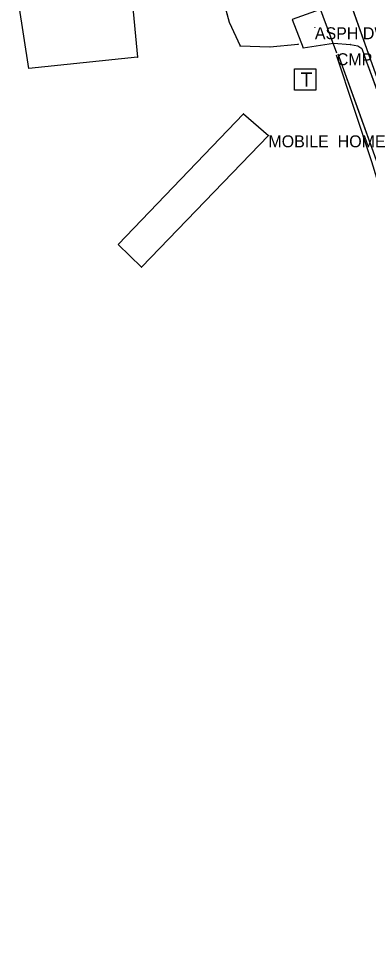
# Model space of a CAD drawing. Extents: x 1050807 to 1053552, y 395828 to 398415.
# Drawn here: x 1052487.3 to 1052633.5, y 395848.9 to 396242.6 of the extents above; entities that cross this region are included whole.
import ezdxf

# ---------------------------------------------------------------- set-up
doc = ezdxf.new("R2010")
doc.units = 0
for name, color, linetype in [('S_BUILDING', 7, 'Continuous'), ('S_BUILDING_ANNOT', 7, 'Continuous'), ('S_DITCHLINE', 7, 'Continuous'), ('S_DRIVEWAY', 7, 'Continuous'), ('S_EDGE_PAVEMENT', 7, 'Continuous'), ('S_MSC_PT_SYM', 7, 'Continuous'), ('S_RDW_PT_SYM', 7, 'Continuous'), ('S_SHOULDER', 7, 'Continuous'), ('S_SIDE_DRAIN', 7, 'Continuous'), ('S_SIDE_DRAIN_ANNOT', 7, 'Continuous'), ('S_STR_PT_SYM', 7, 'Continuous'), ('S_SURVEY_TEXT_ANNOT', 7, 'Continuous'), ('S_TELEPHONE_UTILITIES', 7, 'Continuous')]:
    doc.layers.add(name, color=color, linetype=linetype)

msp = doc.modelspace()

# ---------------------------------------------------------------- linework, layer by layer
at = {"layer": 'S_BUILDING'}
for p, q in [((1052533.83, 396259.23), (1052536.9, 396226.54)), ((1052491.51, 396221.91), (1052487.31, 396248.91)), ((1052536.9, 396226.54), (1052491.51, 396221.91)), ((1052528.92, 396148.24), (1052581.25, 396202.87)), ((1052581.25, 396202.87), (1052591.72, 396193.88)), ((1052591.72, 396193.88), (1052538.7, 396138.79)), ((1052538.7, 396138.79), (1052528.92, 396148.24))]:
    msp.add_line(p, q, dxfattribs=at)
at = {"layer": 'S_DITCHLINE'}
for p, q in [((1052620.07, 396227.58), (1052634.89, 396182.92)), ((1052620.81, 396227.93), (1052636.76, 396183.53))]:
    msp.add_line(p, q, dxfattribs=at)
for points in [[(1052620.07, 396227.58), (1052627.48, 396205.25), (1052634.89, 396182.92), (1052642.05, 396159.3), (1052649.2, 396135.67), (1052656.36, 396112.05), (1052663.51, 396088.42), (1052668.48, 396075.25), (1052673.44, 396062.07), (1052678.41, 396048.9), (1052683.38, 396035.72), (1052688.34, 396022.55), (1052693.31, 396009.37), (1052698.27, 395996.19), (1052703.24, 395983.02), (1052710.64, 395963.11), (1052718.05, 395943.2), (1052725.45, 395923.3), (1052732.85, 395903.39), (1052737.44, 395889.76), (1052742.03, 395876.12), (1052746.61, 395862.49), (1052751.2, 395848.85)], [(1052620.81, 396227.93), (1052628.79, 396205.73), (1052636.76, 396183.53), (1052644, 396159.99), (1052651.24, 396136.44), (1052658.48, 396112.9), (1052665.73, 396089.35), (1052670.69, 396076.19), (1052675.66, 396063.03), (1052680.63, 396049.86), (1052685.59, 396036.7), (1052690.56, 396023.54), (1052695.53, 396010.38), (1052700.49, 395997.21), (1052705.46, 395984.05), (1052713.07, 395964.14), (1052720.69, 395944.23), (1052728.3, 395924.32), (1052735.92, 395904.41), (1052740.3, 395890.61), (1052744.69, 395876.8), (1052749.07, 395863), (1052753.46, 395849.2)]]:
    msp.add_lwpolyline(points, dxfattribs=at)
at = {"layer": 'S_DRIVEWAY'}
for p, q in [((1052572.02, 396253.63), (1052575.27, 396241.22)), ((1052613.38, 396246.47), (1052601.72, 396242.34)), ((1052575.27, 396241.22), (1052579.85, 396231.29)), ((1052601.72, 396242.34), (1052606.28, 396230.47)), ((1052579.85, 396231.29), (1052592.36, 396230.88)), ((1052592.36, 396230.88), (1052604.22, 396232.06)), ((1052606.28, 396230.47), (1052618.94, 396232.39)), ((1052618.94, 396232.39), (1052626, 396231.88)), ((1052626, 396231.88), (1052629.12, 396231.28))]:
    msp.add_line(p, q, dxfattribs=at)
for points in [[(1052582.95, 396285.88), (1052574.93, 396278.66), (1052570.6, 396269.39), (1052572.02, 396253.63), (1052575.27, 396241.22), (1052579.85, 396231.29), (1052592.36, 396230.88), (1052604.22, 396232.06)], [(1052621.14, 396254.58), (1052618.12, 396249.9), (1052613.38, 396246.47), (1052601.72, 396242.34), (1052606.28, 396230.47), (1052618.94, 396232.39), (1052626, 396231.88), (1052629.12, 396231.28)]]:
    msp.add_lwpolyline(points, dxfattribs=at)
at = {"layer": 'S_EDGE_PAVEMENT'}
msp.add_line((1052623.98, 396255.21), (1052634.42, 396225.5), dxfattribs=at)
msp.add_lwpolyline([(1052623.98, 396255.21), (1052629.2, 396240.35), (1052634.42, 396225.5), (1052641.29, 396206.33), (1052648.17, 396187.15), (1052655.4, 396166.58), (1052662.63, 396146), (1052669.81, 396125.89), (1052676.99, 396105.79), (1052684.26, 396085.26), (1052691.54, 396064.73), (1052698.54, 396044.92), (1052705.54, 396025.11), (1052713.26, 396003.75), (1052720.98, 395982.38), (1052728.49, 395960.93), (1052736.01, 395939.48), (1052742.94, 395919.92), (1052749.87, 395900.35), (1052754.46, 395887.56), (1052759.05, 395874.76), (1052766.38, 395854.19)], dxfattribs=at)
at = {"layer": 'S_MSC_PT_SYM'}
msp.add_lwpolyline([(1052611.16, 396239.08), (1052611.16, 396239.13), (1052611.16, 396239.08), (1052611.11, 396239.08), (1052611.16, 396239.08), (1052611.16, 396239.03), (1052611.16, 396239.08), (1052611.21, 396239.08)], dxfattribs=at)
at = {"layer": 'S_RDW_PT_SYM'}
for points in [[(1052575.27, 396241.22), (1052575.27, 396241.27), (1052575.27, 396241.22), (1052575.22, 396241.22), (1052575.27, 396241.22), (1052575.27, 396241.17), (1052575.27, 396241.22), (1052575.32, 396241.22)], [(1052601.72, 396242.34), (1052601.72, 396242.39), (1052601.72, 396242.34), (1052601.67, 396242.34), (1052601.72, 396242.34), (1052601.72, 396242.29), (1052601.72, 396242.34), (1052601.77, 396242.34)], [(1052579.85, 396231.29), (1052579.85, 396231.34), (1052579.85, 396231.29), (1052579.8, 396231.29), (1052579.85, 396231.29), (1052579.85, 396231.24), (1052579.85, 396231.29), (1052579.9, 396231.29)], [(1052604.22, 396232.06), (1052604.22, 396232.11), (1052604.22, 396232.06), (1052604.17, 396232.06), (1052604.22, 396232.06), (1052604.22, 396232.01), (1052604.22, 396232.06), (1052604.27, 396232.06)], [(1052618.94, 396232.39), (1052618.94, 396232.44), (1052618.94, 396232.39), (1052618.89, 396232.39), (1052618.94, 396232.39), (1052618.94, 396232.34), (1052618.94, 396232.39), (1052618.99, 396232.39)], [(1052626, 396231.88), (1052626, 396231.93), (1052626, 396231.88), (1052625.95, 396231.88), (1052626, 396231.88), (1052626, 396231.83), (1052626, 396231.88), (1052626.05, 396231.88)], [(1052629.12, 396231.28), (1052629.12, 396231.33), (1052629.12, 396231.28), (1052629.07, 396231.28), (1052629.12, 396231.28), (1052629.12, 396231.23), (1052629.12, 396231.28), (1052629.17, 396231.28)], [(1052629.12, 396231.28), (1052629.12, 396231.33), (1052629.12, 396231.28), (1052629.07, 396231.28), (1052629.12, 396231.28), (1052629.12, 396231.23), (1052629.12, 396231.28), (1052629.17, 396231.28)], [(1052592.36, 396230.88), (1052592.36, 396230.93), (1052592.36, 396230.88), (1052592.31, 396230.88), (1052592.36, 396230.88), (1052592.36, 396230.83), (1052592.36, 396230.88), (1052592.41, 396230.88)], [(1052606.28, 396230.47), (1052606.28, 396230.52), (1052606.28, 396230.47), (1052606.23, 396230.47), (1052606.28, 396230.47), (1052606.28, 396230.42), (1052606.28, 396230.47), (1052606.33, 396230.47)], [(1052630.77, 396230.22), (1052630.77, 396230.27), (1052630.77, 396230.22), (1052630.72, 396230.22), (1052630.77, 396230.22), (1052630.77, 396230.17), (1052630.77, 396230.22), (1052630.82, 396230.22)], [(1052632.79, 396224.61), (1052632.79, 396224.66), (1052632.79, 396224.61), (1052632.74, 396224.61), (1052632.79, 396224.61), (1052632.79, 396224.56), (1052632.79, 396224.61), (1052632.84, 396224.61)]]:
    msp.add_lwpolyline(points, dxfattribs=at)
at = {"layer": 'S_SHOULDER'}
for p, q in [((1052629.12, 396231.28), (1052630.77, 396230.22)), ((1052630.77, 396230.22), (1052632.79, 396224.61)), ((1052632.79, 396224.61), (1052646.77, 396186.52))]:
    msp.add_line(p, q, dxfattribs=at)
msp.add_lwpolyline([(1052629.12, 396231.28), (1052630.77, 396230.22), (1052632.79, 396224.61), (1052639.78, 396205.57), (1052646.77, 396186.52), (1052653.85, 396166), (1052660.94, 396145.49), (1052668.04, 396125.3), (1052675.13, 396105.12), (1052682.44, 396084.73), (1052689.75, 396064.34), (1052696.82, 396044.39), (1052703.9, 396024.43), (1052711.34, 396003.05), (1052718.79, 395981.67), (1052726.33, 395960.3), (1052733.88, 395938.93), (1052740.96, 395919.42), (1052748.04, 395899.9), (1052752.59, 395886.84), (1052757.15, 395873.79), (1052764.55, 395853.95)], dxfattribs=at)
at = {"layer": 'S_SIDE_DRAIN'}
msp.add_line((1052620.32, 396228.22), (1052611.96, 396250.8), dxfattribs=at)
at = {"layer": 'S_STR_PT_SYM'}
for points in [[(1052536.9, 396226.54), (1052536.9, 396226.59), (1052536.9, 396226.54), (1052536.85, 396226.54), (1052536.9, 396226.54), (1052536.9, 396226.49), (1052536.9, 396226.54), (1052536.95, 396226.54)], [(1052491.51, 396221.91), (1052491.51, 396221.96), (1052491.51, 396221.91), (1052491.46, 396221.91), (1052491.51, 396221.91), (1052491.51, 396221.86), (1052491.51, 396221.91), (1052491.56, 396221.91)], [(1052581.25, 396202.87), (1052581.25, 396202.92), (1052581.25, 396202.87), (1052581.2, 396202.87), (1052581.25, 396202.87), (1052581.25, 396202.82), (1052581.25, 396202.87), (1052581.3, 396202.87)], [(1052591.72, 396193.88), (1052591.72, 396193.93), (1052591.72, 396193.88), (1052591.67, 396193.88), (1052591.72, 396193.88), (1052591.72, 396193.83), (1052591.72, 396193.88), (1052591.77, 396193.88)], [(1052528.92, 396148.24), (1052528.92, 396148.29), (1052528.92, 396148.24), (1052528.87, 396148.24), (1052528.92, 396148.24), (1052528.92, 396148.19), (1052528.92, 396148.24), (1052528.97, 396148.24)], [(1052538.7, 396138.79), (1052538.7, 396138.84), (1052538.7, 396138.79), (1052538.65, 396138.79), (1052538.7, 396138.79), (1052538.7, 396138.74), (1052538.7, 396138.79), (1052538.75, 396138.79)]]:
    msp.add_lwpolyline(points, dxfattribs=at)
at = {"layer": 'S_TELEPHONE_UTILITIES'}
msp.add_lwpolyline([(1052602.63, 396212.72), (1052602.63, 396221.72), (1052611.63, 396221.72), (1052611.63, 396212.72)], close=True, dxfattribs=at)

# ---------------------------------------------------------------- texts
at = {"layer": 'S_BUILDING_ANNOT'}
msp.add_text('MOBILE  HOME', height=5, dxfattribs=at).set_placement((1052591.72, 396188.88))
at = {"layer": 'S_SIDE_DRAIN_ANNOT'}
msp.add_text('CMP 26 20 0', height=5, dxfattribs=at).set_placement((1052620.32, 396223.22))
at = {"layer": 'S_SURVEY_TEXT_ANNOT'}
msp.add_text('ASPH DW TO MOBILE HOME', height=5, dxfattribs=at).set_placement((1052611.16, 396234.08))
at = {"layer": 'S_TELEPHONE_UTILITIES'}
msp.add_text('T', height=6, dxfattribs=at).set_placement((1052605.19, 396214.22))

doc.saveas('drawing.dxf')
